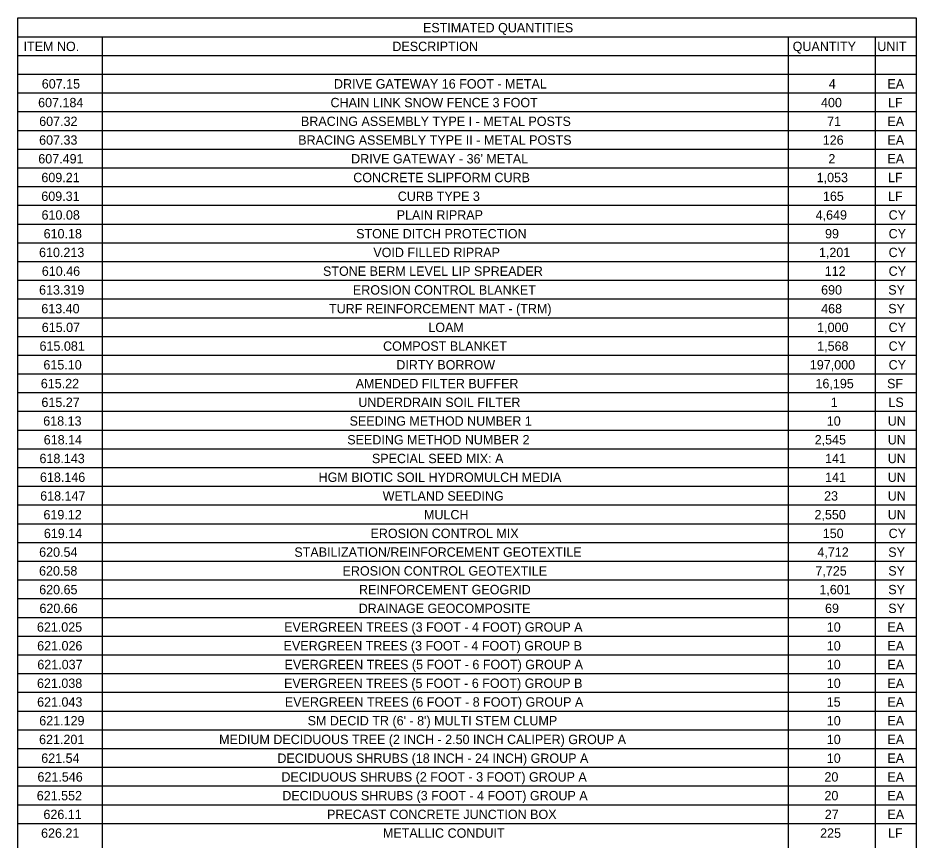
# Model space of a CAD drawing. Extents: x -18.7 to 5.6, y -2.7 to 5.1.
# Drawn here: x -6.23 to -5.286, y 0.554 to 1.418 of the extents above; entities that cross this region are included whole.
import ezdxf

# ---------------------------------------------------------------- set-up
doc = ezdxf.new("R2010")
doc.units = 0
doc.layers.add('ANNOTATION', color=7, linetype='Continuous')
doc.layers.add('BORDER', color=7, linetype='Continuous')

msp = doc.modelspace()

# ---------------------------------------------------------------- linework, layer by layer
at = {"layer": 'BORDER'}
for p, q in [((-6.23036, 1.39863), (-5.28608, 1.39863)), ((-6.14178, 1.39863), (-6.14178, -0.31405)), ((-5.42047, 1.39863), (-5.42047, -0.31405)), ((-5.32908, 1.39863), (-5.32908, -0.31405)), ((-6.23036, 1.37895), (-5.28608, 1.37895)), ((-6.23036, 1.35926), (-5.28608, 1.35926)), ((-6.23036, 1.33957), (-5.28608, 1.33957)), ((-6.23036, 1.31989), (-5.28608, 1.31989)), ((-6.23036, 1.3002), (-5.28608, 1.3002)), ((-6.23036, 1.28052), (-5.28608, 1.28052)), ((-6.23036, 1.26083), (-5.28608, 1.26083)), ((-6.23036, 1.24114), (-5.28608, 1.24114)), ((-6.23036, 1.22146), (-5.28608, 1.22146)), ((-6.23036, 1.20177), (-5.28608, 1.20177)), ((-6.23036, 1.18209), (-5.28608, 1.18209)), ((-6.23036, 1.1624), (-5.28608, 1.1624)), ((-6.23036, 1.14271), (-5.28608, 1.14271)), ((-6.23036, 1.12303), (-5.28608, 1.12303)), ((-6.23036, 1.10334), (-5.28608, 1.10334)), ((-6.23036, 1.08366), (-5.28608, 1.08366)), ((-6.23036, 1.06397), (-5.28608, 1.06397)), ((-6.23036, 1.04428), (-5.28608, 1.04428)), ((-6.23036, 1.0246), (-5.28608, 1.0246)), ((-6.23036, 1.00491), (-5.28608, 1.00491)), ((-6.23036, 0.98523), (-5.28608, 0.98523)), ((-6.23036, 0.96554), (-5.28608, 0.96554)), ((-6.23036, 0.94585), (-5.28608, 0.94585)), ((-6.23036, 0.92617), (-5.28608, 0.92617)), ((-6.23036, 0.90648), (-5.28608, 0.90648)), ((-6.23036, 0.8868), (-5.28608, 0.8868)), ((-6.23036, 0.86711), (-5.28608, 0.86711)), ((-6.23036, 0.84742), (-5.28608, 0.84742)), ((-6.23036, 0.82774), (-5.28608, 0.82774)), ((-6.23036, 0.80805), (-5.28608, 0.80805)), ((-6.23036, 0.78837), (-5.28608, 0.78837)), ((-6.23036, 0.76868), (-5.28608, 0.76868)), ((-6.23036, 0.74899), (-5.28608, 0.74899)), ((-6.23036, 0.72931), (-5.28608, 0.72931)), ((-6.23036, 0.70962), (-5.28608, 0.70962)), ((-6.23036, 0.68994), (-5.28608, 0.68994)), ((-6.23036, 0.67025), (-5.28608, 0.67025)), ((-6.23036, 0.65056), (-5.28608, 0.65056)), ((-6.23036, 0.63088), (-5.28608, 0.63088)), ((-6.23036, 0.61119), (-5.28608, 0.61119)), ((-6.23036, 0.59151), (-5.28608, 0.59151)), ((-6.23036, 0.57182), (-5.28608, 0.57182))]:
    msp.add_line(p, q, dxfattribs=at)
msp.add_lwpolyline([(-6.23036, 1.41832), (-5.28608, 1.41832), (-5.28608, -0.31405), (-6.23036, -0.31405)], close=True, dxfattribs=at)

# ---------------------------------------------------------------- texts
at = {"layer": 'ANNOTATION'}
for s, height, p in [('607.15', 0.009843, (-6.20532, 1.34417)), ('DRIVE GATEWAY 16 FOOT - METAL', 0.009843, (-5.8981, 1.34417)), ('4', 0.00984, (-5.37782, 1.34417)), ('EA', 0.009843, (-5.31615, 1.34417)), ('607.184', 0.009843, (-6.20916, 1.32448)), ('CHAIN LINK SNOW FENCE 3 FOOT', 0.009843, (-5.90174, 1.32448)), ('400', 0.009843, (-5.38603, 1.32448)), ('LF', 0.009843, (-5.31553, 1.32448)), ('607.32', 0.009843, (-6.20803, 1.3048)), ('BRACING ASSEMBLY TYPE I - METAL POSTS', 0.009843, (-5.9328, 1.3048)), ('71', 0.009843, (-5.37953, 1.3048)), ('EA', 0.009843, (-5.31615, 1.3048)), ('607.33', 0.009843, (-6.20811, 1.28511)), ('BRACING ASSEMBLY TYPE II - METAL POSTS', 0.009843, (-5.93572, 1.28511)), ('126', 0.009843, (-5.38417, 1.28511)), ('EA', 0.009843, (-5.31615, 1.28511)), ('607.491', 0.009843, (-6.209, 1.26543)), ("DRIVE GATEWAY - 36' METAL", 0.009843, (-5.88006, 1.26543)), ('2', 0.00984, (-5.37825, 1.26543)), ('EA', 0.009843, (-5.31615, 1.26543)), ('609.21', 0.009843, (-6.20575, 1.24574)), ('CONCRETE SLIPFORM CURB', 0.009843, (-5.87782, 1.24574)), ('1,053', 0.009843, (-5.39056, 1.24574)), ('LF', 0.009843, (-5.31553, 1.24574)), ('609.31', 0.009843, (-6.20582, 1.22605)), ('CURB TYPE 3', 0.009843, (-5.83098, 1.22605)), ('165', 0.009843, (-5.38398, 1.22605)), ('LF', 0.009843, (-5.31553, 1.22605)), ('610.08', 0.009843, (-6.20555, 1.20637)), ('PLAIN RIPRAP', 0.009843, (-5.83213, 1.20637)), ('4,649', 0.009843, (-5.39161, 1.20637)), ('CY', 0.009843, (-5.31491, 1.20637)), ('610.18', 0.009843, (-6.20338, 1.18668)), ('STONE DITCH PROTECTION', 0.009843, (-5.87476, 1.18668)), ('99', 0.009843, (-5.38177, 1.18668)), ('CY', 0.009843, (-5.31491, 1.18668)), ('610.213', 0.009843, (-6.20818, 1.167)), ('VOID FILLED RIPRAP', 0.009843, (-5.8567, 1.167)), ('1,201', 0.009843, (-5.3882, 1.167)), ('CY', 0.009843, (-5.31491, 1.167)), ('610.46', 0.009843, (-6.20528, 1.14731)), ('STONE BERM LEVEL LIP SPREADER', 0.009843, (-5.90962, 1.14731)), ('112', 0.009843, (-5.38212, 1.14731)), ('CY', 0.009843, (-5.31491, 1.14731)), ('613.319', 0.009843, (-6.20815, 1.12762)), ('EROSION CONTROL BLANKET', 0.009843, (-5.87816, 1.12762)), ('690', 0.009843, (-5.38588, 1.12762)), ('SY', 0.009843, (-5.3153, 1.12762)), ('613.40', 0.009843, (-6.20582, 1.10794)), ('TURF REINFORCEMENT MAT - (TRM)', 0.009843, (-5.90331, 1.10794)), ('468', 0.009843, (-5.38584, 1.10794)), ('SY', 0.009843, (-5.3153, 1.10794)), ('615.07', 0.009843, (-6.20536, 1.08825)), ('LOAM', 0.009843, (-5.79884, 1.08825)), ('1,000', 0.009843, (-5.39006, 1.08825)), ('CY', 0.009843, (-5.31491, 1.08825)), ('615.081', 0.009843, (-6.20768, 1.06857)), ('COMPOST BLANKET', 0.009843, (-5.84646, 1.06857)), ('1,568', 0.009843, (-5.39002, 1.06857)), ('CY', 0.009843, (-5.31491, 1.06857)), ('615.10', 0.009843, (-6.20358, 1.04888)), ('DIRTY BORROW', 0.009843, (-5.83255, 1.04888)), ('197,000', 0.009843, (-5.39773, 1.04888)), ('CY', 0.009843, (-5.31491, 1.04888)), ('615.22', 0.009843, (-6.20633, 1.02919)), ('AMENDED FILTER BUFFER ', 0.009843, (-5.87526, 1.02919)), ('16,195', 0.009843, (-5.3918, 1.02919)), ('SF', 0.009843, (-5.31654, 1.02919)), ('615.27', 0.009843, (-6.20567, 1.00951)), ('UNDERDRAIN SOIL FILTER', 0.009843, (-5.87243, 1.00951)), ('1', 0.00984, (-5.37581, 1.00951)), ('LS', 0.009843, (-5.31511, 1.00951)), ('618.13', 0.009843, (-6.20377, 0.98982)), ('SEEDING METHOD NUMBER 1', 0.009843, (-5.88167, 0.98982)), ('10', 0.009843, (-5.37991, 0.98982)), ('UN', 0.009843, (-5.31584, 0.98982)), ('618.14', 0.009843, (-6.20326, 0.97014)), ('SEEDING METHOD NUMBER 2', 0.009843, (-5.88411, 0.97014)), ('2,545', 0.009843, (-5.39265, 0.97014)), ('UN', 0.009843, (-5.31584, 0.97014)), ('618.143', 0.009843, (-6.20772, 0.95045)), ('SPECIAL SEED MIX: A', 0.009843, (-5.85818, 0.95045)), ('141', 0.009843, (-5.38169, 0.95045)), ('UN', 0.009843, (-5.31584, 0.95045)), ('618.146', 0.009843, (-6.20722, 0.93076)), ('HGM BIOTIC SOIL HYDROMULCH MEDIA', 0.009843, (-5.91423, 0.93076)), ('141', 0.009843, (-5.38169, 0.93076)), ('UN', 0.009843, (-5.31584, 0.93076)), ('618.147', 0.009843, (-6.20698, 0.91108)), ('WETLAND SEEDING', 0.009843, (-5.84686, 0.91108)), ('23', 0.009843, (-5.38274, 0.91108)), ('UN', 0.009843, (-5.31584, 0.91108)), ('619.12', 0.009843, (-6.20354, 0.89139)), ('MULCH', 0.009843, (-5.80343, 0.89139)), ('2,550', 0.009843, (-5.39285, 0.89139)), ('UN', 0.009843, (-5.31584, 0.89139)), ('619.14', 0.009843, (-6.20311, 0.87171)), ('EROSION CONTROL MIX', 0.009843, (-5.85968, 0.87171)), ('150', 0.009843, (-5.38418, 0.87171)), ('CY', 0.009843, (-5.31491, 0.87171)), ('620.54', 0.009843, (-6.20807, 0.85202)), ('STABILIZATION/REINFORCEMENT GEOTEXTILE', 0.009843, (-5.93973, 0.85202)), ('4,712', 0.009843, (-5.38979, 0.85202)), ('SY', 0.009843, (-5.3153, 0.85202)), ('620.58', 0.009843, (-6.20819, 0.83233)), ('EROSION CONTROL GEOTEXTILE', 0.009843, (-5.88907, 0.83233)), ('7,725', 0.009843, (-5.39188, 0.83233)), ('SY', 0.009843, (-5.3153, 0.83233)), ('620.65', 0.009843, (-6.20803, 0.81265)), ('REINFORCEMENT GEOGRID', 0.009843, (-5.8718, 0.81265)), ('1,601', 0.009843, (-5.38773, 0.81265)), ('SY', 0.009843, (-5.3153, 0.81265)), ('620.66', 0.009843, (-6.20776, 0.79296)), ('DRAINAGE GEOCOMPOSITE', 0.009843, (-5.87212, 0.79296)), ('69', 0.009843, (-5.38177, 0.79296)), ('SY', 0.009843, (-5.3153, 0.79296)), ('621.025', 0.009843, (-6.21043, 0.77328)), ('EVERGREEN TREES (3 FOOT - 4 FOOT) GROUP A', 0.009843, (-5.95048, 0.77328)), ('10', 0.009843, (-5.37991, 0.77328)), ('EA', 0.009843, (-5.31615, 0.77328)), ('621.026', 0.009843, (-6.21016, 0.75359)), ('EVERGREEN TREES (3 FOOT - 4 FOOT) GROUP B', 0.009843, (-5.95106, 0.75359)), ('10', 0.009843, (-5.37991, 0.75359)), ('EA', 0.009843, (-5.31615, 0.75359)), ('621.037', 0.009843, (-6.21001, 0.7339)), ('EVERGREEN TREES (5 FOOT - 6 FOOT) GROUP A', 0.009843, (-5.95002, 0.7339)), ('10', 0.009843, (-5.37991, 0.7339)), ('EA', 0.009843, (-5.31615, 0.7339)), ('621.038', 0.009843, (-6.21035, 0.71422)), ('EVERGREEN TREES (5 FOOT - 6 FOOT) GROUP B', 0.009843, (-5.9506, 0.71422)), ('10', 0.009843, (-5.37991, 0.71422)), ('EA', 0.009843, (-5.31615, 0.71422)), ('621.043', 0.009843, (-6.2102, 0.69453)), ('EVERGREEN TREES (6 FOOT - 8 FOOT) GROUP A', 0.009843, (-5.94971, 0.69453)), ('15', 0.009843, (-5.38003, 0.69453)), ('EA', 0.009843, (-5.31615, 0.69453)), ('621.129', 0.009843, (-6.20799, 0.67485)), ("SM DECID TR (6' - 8') MULTI STEM CLUMP", 0.009843, (-5.92579, 0.67485)), ('10', 0.009843, (-5.37991, 0.67485)), ('EA', 0.009843, (-5.31615, 0.67485)), ('621.201', 0.009843, (-6.20815, 0.65516)), ('MEDIUM DECIDUOUS TREE (2 INCH - 2.50 INCH CALIPER) GROUP A', 0.009843, (-6.01886, 0.65516)), ('10', 0.009843, (-5.37991, 0.65516)), ('EA', 0.009843, (-5.31615, 0.65516)), ('621.54', 0.009843, (-6.2059, 0.63547)), ('DECIDUOUS SHRUBS (18 INCH - 24 INCH) GROUP A', 0.009843, (-5.95755, 0.63547)), ('10', 0.009843, (-5.37991, 0.63547)), ('EA', 0.009843, (-5.31615, 0.63547)), ('621.546', 0.009843, (-6.20985, 0.61579)), ('DECIDUOUS SHRUBS (2 FOOT - 3 FOOT) GROUP A', 0.009843, (-5.95334, 0.61579)), ('20', 0.009843, (-5.38239, 0.61579)), ('EA', 0.009843, (-5.31615, 0.61579)), ('621.552', 0.009843, (-6.21059, 0.5961)), ('DECIDUOUS SHRUBS (3 FOOT - 4 FOOT) GROUP A', 0.009843, (-5.95241, 0.5961)), ('20', 0.009843, (-5.38239, 0.5961)), ('EA', 0.009843, (-5.31615, 0.5961)), ('626.11', 0.009843, (-6.20357, 0.57642)), ('PRECAST CONCRETE JUNCTION BOX', 0.009843, (-5.90537, 0.57642)), ('27', 0.009843, (-5.38201, 0.57642)), ('EA', 0.009843, (-5.31615, 0.57642)), ('626.21', 0.009843, (-6.20606, 0.55673)), ('METALLIC CONDUIT', 0.009843, (-5.84666, 0.55673)), ('225', 0.009843, (-5.38693, 0.55673)), ('LF', 0.009843, (-5.31553, 0.55673))]:
    msp.add_text(s, height=height, dxfattribs=at).set_placement(p)
at = {"layer": 'BORDER'}
for s, height, p in [('ESTIMATED QUANTITIES', 0.0098425, (-5.80451, 1.40323)), ('ITEM NO.', 0.009843, (-6.22446, 1.38354)), ('DESCRIPTION', 0.0098425, (-5.83666, 1.38354)), ('QUANTITY', 0.009843, (-5.41578, 1.38354)), ('UNIT', 0.009843, (-5.32677, 1.38354))]:
    msp.add_text(s, height=height, dxfattribs=at).set_placement(p)

doc.saveas('drawing.dxf')
